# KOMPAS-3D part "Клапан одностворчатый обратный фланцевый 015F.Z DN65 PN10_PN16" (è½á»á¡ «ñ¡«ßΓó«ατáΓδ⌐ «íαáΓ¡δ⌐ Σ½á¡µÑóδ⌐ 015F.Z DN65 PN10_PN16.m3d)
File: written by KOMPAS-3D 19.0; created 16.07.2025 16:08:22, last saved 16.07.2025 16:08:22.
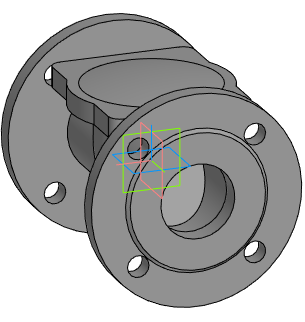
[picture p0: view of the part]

Document properties: Полное имя файла: E:\Dendor Работа Сачек\3D для проектировщиков\5.4 Тип 015F.Z. Клапан одностворчатый обратный фланцевый\stp_Клапан одностворчатый обратный фланцевый 015F.Z PN10_16\Клапан одностворчатый обратный фланцевый 015F.Z DN65 PN10_PN16.m3d

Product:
- Part/product: Клапан одностворчатый обратный фланцевый 015F.Z DN65 PN10_PN16

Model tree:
1. Операция без истории:1
2. Операция без истории:2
